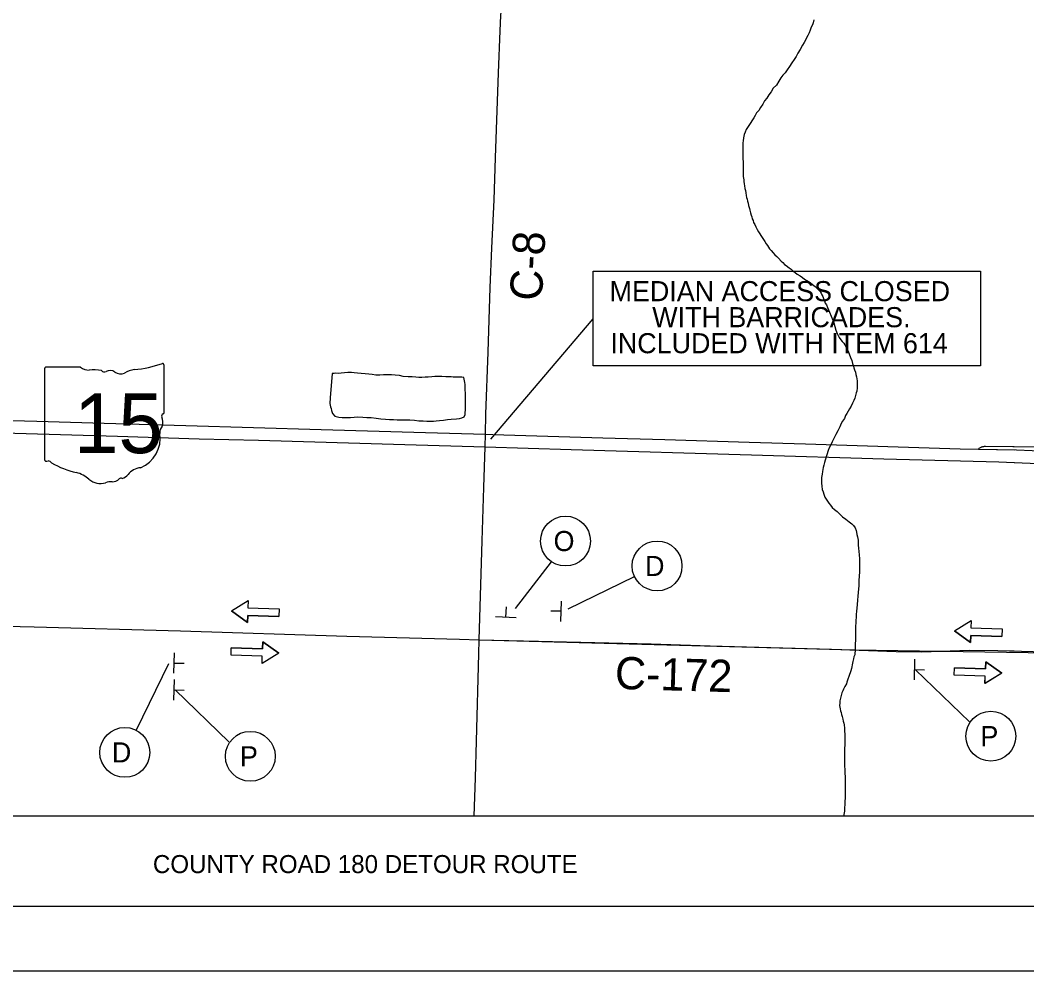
# Model space of a CAD drawing. Extents: x 1 to 1971, y -2 to 1107.
# Drawn here: x 1660.16 to 1667.97, y 1084.6 to 1091.98 of the extents above; entities that cross this region are included whole.
import ezdxf

# ---------------------------------------------------------------- set-up
doc = ezdxf.new("R2010")
doc.units = 0
for name, color, linetype in [('GM_X_County_Road', 7, 'Continuous'), ('GM_X_County_Road_Text', 7, 'Continuous'), ('GM_X_Interchange_Ramps', 7, 'Continuous'), ('GM_X_Minor_River', 7, 'Continuous'), ('GM_X_State_Route', 7, 'Continuous'), ('GM_X_State_Shield', 7, 'Continuous'), ('SH_Border', 7, 'Continuous'), ('SH_Cut_Line', 7, 'Continuous'), ('SH_Data', 7, 'Continuous'), ('SH_Text', 7, 'Continuous'), ('SN_P_Signs', 7, 'Continuous')]:
    doc.layers.add(name, color=color, linetype=linetype)

msp = doc.modelspace()

# ---------------------------------------------------------------- linework, layer by layer
at = {"layer": 'GM_X_County_Road'}
for points in [[(1663.7714, 1088.7638), (1663.7757, 1088.9203), (1663.7916, 1089.4012), (1663.8088, 1089.904), (1663.8208, 1090.2091), (1663.8384, 1090.5818), (1663.8499, 1090.9095), (1663.8728, 1091.5685), (1663.885, 1091.8932), (1663.8919, 1092.014), (1663.8966, 1092.0716), (1663.9012, 1092.1103), (1663.9093, 1092.1486), (1663.9186, 1092.1687), (1663.9325, 1092.1954), (1663.9457, 1092.2144), (1663.9663, 1092.2384)], [(1663.7714, 1088.7638), (1663.7757, 1088.9203), (1663.7916, 1089.4012), (1663.8088, 1089.904), (1663.8208, 1090.2091), (1663.8384, 1090.5818), (1663.8499, 1090.9095), (1663.8728, 1091.5685), (1663.885, 1091.8932), (1663.8919, 1092.014), (1663.8966, 1092.0716), (1663.9012, 1092.1103), (1663.9093, 1092.1486), (1663.9186, 1092.1687), (1663.9325, 1092.1954), (1663.9457, 1092.2144), (1663.9663, 1092.2384)], [(1663.7686, 1088.6652), (1663.7714, 1088.7638)], [(1663.7686, 1088.6652), (1663.7714, 1088.7638)], [(1663.7236, 1087.1696), (1663.7452, 1087.9363), (1663.76, 1088.3517), (1663.7686, 1088.6652)], [(1663.7236, 1087.1696), (1663.7452, 1087.9363), (1663.76, 1088.3517), (1663.7686, 1088.6652)], [(1656.5672, 1087.3642), (1656.5934, 1087.3633), (1657.0425, 1087.3482), (1657.533, 1087.3387), (1659.0643, 1087.2977), (1660.2675, 1087.2696), (1661.405, 1087.2377), (1662.6955, 1087.1976), (1663.5705, 1087.1736), (1663.7236, 1087.1696)], [(1656.5672, 1087.3642), (1656.5934, 1087.3633), (1657.0425, 1087.3482), (1657.533, 1087.3387), (1659.0643, 1087.2977), (1660.2675, 1087.2696), (1661.405, 1087.2377), (1662.6955, 1087.1976), (1663.5705, 1087.1736), (1663.7236, 1087.1696)], [(1663.6851, 1085.8005), (1663.6935, 1086.0994), (1663.7027, 1086.3836), (1663.7203, 1087.0616), (1663.7236, 1087.1696)], [(1663.6851, 1085.8005), (1663.6935, 1086.0994), (1663.7027, 1086.3836), (1663.7203, 1087.0616), (1663.7236, 1087.1696)], [(1663.7236, 1087.1696), (1664.183, 1087.1576), (1665.0579, 1087.1385), (1665.5171, 1087.1234), (1666.4577, 1087.0978), (1666.9606, 1087.0776), (1667.1575, 1087.0752), (1667.5292, 1087.089), (1667.748, 1087.0865), (1667.8763, 1087.0829)], [(1663.7236, 1087.1696), (1664.183, 1087.1576), (1665.0579, 1087.1385), (1665.5171, 1087.1234), (1666.4577, 1087.0978), (1666.9606, 1087.0776), (1667.1575, 1087.0752), (1667.5292, 1087.089), (1667.748, 1087.0865), (1669.3011, 1087.0422), (1669.9792, 1087.0232), (1670.236, 1087.0104), (1670.4866, 1086.997), (1670.9021, 1086.9648)]]:
    msp.add_lwpolyline(points, dxfattribs=at)
at = {"layer": 'GM_X_Interchange_Ramps'}
for points in [[(1667.8763, 1088.6662), (1667.6527, 1088.6689), (1667.6472, 1088.6687), (1667.642, 1088.6681), (1667.6368, 1088.6676), (1667.6307, 1088.6666), (1667.6242, 1088.6647), (1667.6203, 1088.6634), (1667.6166, 1088.6617), (1667.6121, 1088.6596), (1667.6075, 1088.6571), (1667.603, 1088.6535), (1667.5998, 1088.6492)], [(1668.0763, 1088.6637), (1667.6527, 1088.6689), (1667.6472, 1088.6687), (1667.642, 1088.6681), (1667.6368, 1088.6676), (1667.6307, 1088.6666), (1667.6242, 1088.6647), (1667.6203, 1088.6634), (1667.6166, 1088.6617), (1667.6121, 1088.6596), (1667.6075, 1088.6571), (1667.603, 1088.6535), (1667.5998, 1088.6492)]]:
    msp.add_lwpolyline(points, dxfattribs=at)
at = {"layer": 'GM_X_Minor_River'}
for points in [[(1666.3202, 1091.9803), (1666.3148, 1091.9563), (1666.3094, 1091.9402), (1666.3013, 1091.9215), (1666.2932, 1091.9001), (1666.2851, 1091.8788), (1666.2744, 1091.8574), (1666.2636, 1091.8387), (1666.2556, 1091.8227), (1666.2448, 1091.804), (1666.2341, 1091.7826), (1666.2153, 1091.7506), (1666.1965, 1091.7212), (1666.183, 1091.6945), (1666.1669, 1091.6705), (1666.1508, 1091.6464), (1666.132, 1091.6171), (1666.1132, 1091.5904), (1666.0971, 1091.569)], [(1666.0971, 1091.569), (1666.081, 1091.5503), (1666.0649, 1091.529), (1666.0488, 1091.5049), (1666.03, 1091.4729), (1666.0059, 1091.4489), (1665.9898, 1091.4222), (1665.971, 1091.3982), (1665.9549, 1091.3715), (1665.9388, 1091.3501), (1665.9253, 1091.3261), (1665.9065, 1091.2994), (1665.8931, 1091.2754), (1665.877, 1091.2567), (1665.8663, 1091.238), (1665.8555, 1091.2193), (1665.8394, 1091.1953), (1665.8313, 1091.1819), (1665.8206, 1091.1686), (1665.7964, 1091.1285), (1665.7883, 1091.1071), (1665.7803, 1091.0911), (1665.7776, 1091.0777), (1665.7749, 1091.0644), (1665.7721, 1091.0403), (1665.7694, 1091.0243), (1665.7694, 1091.0109), (1665.7694, 1090.9948), (1665.7693, 1090.9788), (1665.7693, 1090.9627), (1665.7692, 1090.9413), (1665.7692, 1090.9226), (1665.7691, 1090.9012), (1665.7718, 1090.8771), (1665.7717, 1090.8584), (1665.7717, 1090.8343), (1665.7716, 1090.8075), (1665.7716, 1090.7835), (1665.7715, 1090.7647), (1665.7742, 1090.7513), (1665.7768, 1090.7379), (1665.7768, 1090.7246), (1665.7794, 1090.7059), (1665.782, 1090.6925), (1665.7847, 1090.6711), (1665.79, 1090.655), (1665.7926, 1090.6362), (1665.7953, 1090.6175), (1665.7979, 1090.6015), (1665.8032, 1090.588), (1665.8058, 1090.572), (1665.8112, 1090.5559), (1665.8138, 1090.5399), (1665.8218, 1090.5158), (1665.8244, 1090.5024), (1665.8297, 1090.4809), (1665.835, 1090.4649), (1665.8403, 1090.4515), (1665.843, 1090.4354), (1665.851, 1090.422), (1665.8536, 1090.4059), (1665.8616, 1090.3925), (1665.8696, 1090.3738), (1665.8803, 1090.3524), (1665.8909, 1090.3336), (1665.9203, 1090.2907), (1665.9309, 1090.2746), (1665.9416, 1090.2585), (1665.9496, 1090.2424), (1665.9603, 1090.229), (1665.9683, 1090.2156), (1665.9762, 1090.2022), (1665.9896, 1090.1888), (1666.0056, 1090.1727), (1666.019, 1090.1566), (1666.0323, 1090.1432), (1666.0457, 1090.1298), (1666.067, 1090.1083), (1666.0804, 1090.0976), (1666.0937, 1090.0815), (1666.1071, 1090.0734), (1666.1284, 1090.0546), (1666.1445, 1090.0438), (1666.1578, 1090.0331), (1666.1765, 1090.0197), (1666.1925, 1090.0062), (1666.2139, 1089.9928), (1666.2326, 1089.9793), (1666.2486, 1089.9686), (1666.2673, 1089.9578), (1666.2914, 1089.9417), (1666.3101, 1089.9256), (1666.3315, 1089.9095), (1666.3448, 1089.8987), (1666.3582, 1089.8853), (1666.3688, 1089.8719), (1666.3768, 1089.8585), (1666.3821, 1089.8451), (1666.3901, 1089.8317), (1666.3955, 1089.8183), (1666.4034, 1089.7995)], [(1666.4034, 1089.7995), (1666.4087, 1089.7808), (1666.4194, 1089.7674), (1666.4274, 1089.7486), (1666.4354, 1089.7299), (1666.4434, 1089.7111), (1666.4673, 1089.6495), (1666.4753, 1089.6281), (1666.4833, 1089.6013), (1666.4912, 1089.5718), (1666.5019, 1089.5451), (1666.5179, 1089.5156), (1666.5312, 1089.4968), (1666.5419, 1089.4834), (1666.5525, 1089.47), (1666.5605, 1089.4566), (1666.5685, 1089.4432), (1666.5765, 1089.4298), (1666.5872, 1089.4083), (1666.5952, 1089.3869), (1666.6058, 1089.3601), (1666.6164, 1089.336), (1666.6217, 1089.3119), (1666.6297, 1089.2931), (1666.6324, 1089.2798), (1666.6377, 1089.2637), (1666.643, 1089.2449), (1666.6456, 1089.2289), (1666.6509, 1089.2101), (1666.6536, 1089.1941), (1666.6562, 1089.178), (1666.6562, 1089.162), (1666.6561, 1089.1405), (1666.6561, 1089.1245), (1666.6534, 1089.0978), (1666.6507, 1089.0844), (1666.6453, 1089.0657), (1666.6399, 1089.0443), (1666.6318, 1089.0256), (1666.621, 1089.0042), (1666.6103, 1088.9829), (1666.5969, 1088.9615), (1666.5861, 1088.9428), (1666.578, 1088.9241), (1666.5673, 1088.9108), (1666.5592, 1088.8867), (1666.5431, 1088.8653), (1666.5324, 1088.8467), (1666.5216, 1088.8226), (1666.5082, 1088.7905), (1666.492, 1088.7612), (1666.4759, 1088.7318), (1666.4625, 1088.7051), (1666.4517, 1088.681), (1666.441, 1088.6597), (1666.4329, 1088.6383), (1666.4086, 1088.5635), (1666.4032, 1088.5447), (1666.3978, 1088.5233), (1666.3925, 1088.5073), (1666.3897, 1088.4913), (1666.387, 1088.4752), (1666.3843, 1088.4538), (1666.3816, 1088.4298), (1666.3815, 1088.4084), (1666.3815, 1088.3843), (1666.3841, 1088.3602), (1666.3867, 1088.3361), (1666.392, 1088.3174), (1666.3973, 1088.2986), (1666.4053, 1088.2772), (1666.416, 1088.2611), (1666.4266, 1088.245), (1666.4373, 1088.2289), (1666.4506, 1088.2128), (1666.464, 1088.1967), (1666.48, 1088.1806), (1666.5014, 1088.1645), (1666.5254, 1088.1403), (1666.5441, 1088.1242), (1666.5681, 1088.1054), (1666.5948, 1088.0839), (1666.6162, 1088.0678), (1666.6296, 1088.0571), (1666.6429, 1088.0383), (1666.6482, 1088.0169), (1666.6508, 1088.0035), (1666.6535, 1087.9874), (1666.6588, 1087.9687), (1666.6614, 1087.9553), (1666.6641, 1087.9419), (1666.664, 1087.9232), (1666.664, 1087.9045), (1666.6666, 1087.8804), (1666.6692, 1087.8536), (1666.6719, 1087.8295), (1666.6744, 1087.7974), (1666.6744, 1087.776), (1666.6743, 1087.7493), (1666.6743, 1087.7252), (1666.6742, 1087.6957)], [(1662.5812, 1089.2365), (1662.5647, 1089.0466), (1662.5646, 1089.0038), (1662.5672, 1088.9771), (1662.5725, 1088.9637), (1662.5751, 1088.9476), (1662.5831, 1088.9262), (1662.6018, 1088.9047), (1662.6339, 1088.8966), (1662.658, 1088.8938), (1662.6713, 1088.8938), (1662.6874, 1088.8937), (1662.7061, 1088.8937), (1662.7249, 1088.8936), (1662.7516, 1088.8962), (1662.7811, 1088.8988), (1662.8185, 1088.896), (1662.8506, 1088.8932), (1662.8854, 1088.8931), (1662.9228, 1088.8876), (1662.9603, 1088.8848), (1662.9951, 1088.8821), (1663.0272, 1088.8793), (1663.0566, 1088.8792), (1663.086, 1088.8764), (1663.1128, 1088.8763), (1663.1422, 1088.8762), (1663.1851, 1088.8761), (1663.2198, 1088.8733), (1663.2546, 1088.8679), (1663.2867, 1088.8677), (1663.3161, 1088.865), (1663.3429, 1088.8649), (1663.367, 1088.8648), (1663.3884, 1088.8674), (1663.4151, 1088.87), (1663.4446, 1088.8726), (1663.4767, 1088.8778), (1663.5061, 1088.8804), (1663.5463, 1088.883), (1663.5704, 1088.8856), (1663.5891, 1088.8909), (1663.6052, 1088.8988), (1663.6133, 1088.9175), (1663.6133, 1088.9309), (1663.616, 1088.9523), (1663.6161, 1088.9978), (1663.6162, 1089.0138), (1663.6162, 1089.0326), (1663.6162, 1089.0486)], [(1663.6162, 1089.0486), (1663.6163, 1089.0673), (1663.6163, 1089.0834), (1663.6137, 1089.1075), (1663.6137, 1089.1289), (1663.6138, 1089.1503), (1663.6112, 1089.1664), (1663.6085, 1089.1797), (1663.6032, 1089.2038), (1663.5872, 1089.2066), (1663.5738, 1089.2066), (1663.5551, 1089.2067), (1663.5363, 1089.2067), (1663.5203, 1089.2068), (1663.5042, 1089.2095), (1663.4855, 1089.2096), (1663.4641, 1089.2096), (1663.432, 1089.2124), (1663.4025, 1089.2125), (1663.3785, 1089.2126), (1663.3544, 1089.21), (1663.3276, 1089.2074), (1663.3035, 1089.2075), (1663.2768, 1089.2049), (1663.2554, 1089.2049), (1663.2313, 1089.2077), (1663.2019, 1089.2105), (1663.1724, 1089.2106), (1663.1323, 1089.2134), (1663.1029, 1089.2188), (1663.0708, 1089.2216), (1663.0413, 1089.2244), (1663.0119, 1089.2245), (1662.9798, 1089.2246), (1662.9504, 1089.222), (1662.9209, 1089.2221), (1662.8915, 1089.2275), (1662.8648, 1089.2303), (1662.7792, 1089.2386), (1662.7524, 1089.2413), (1662.731, 1089.2441), (1662.7043, 1089.2442), (1662.6775, 1089.2416), (1662.6507, 1089.239), (1662.6293, 1089.2364), (1662.6106, 1089.2391), (1662.5972, 1089.2365), (1662.5865, 1089.2365), (1662.5812, 1089.2365)], [(1666.6742, 1087.6957), (1666.6714, 1087.6289), (1666.6713, 1087.6101), (1666.6713, 1087.5887), (1666.6686, 1087.5647), (1666.6658, 1087.5352), (1666.6631, 1087.5085), (1666.6603, 1087.4764), (1666.6576, 1087.4443), (1666.6548, 1087.4149), (1666.6521, 1087.3908), (1666.6494, 1087.3667), (1666.6493, 1087.3427), (1666.6466, 1087.3213), (1666.6465, 1087.2972), (1666.6438, 1087.2785), (1666.6438, 1087.2544), (1666.6437, 1087.2196), (1666.6436, 1087.1902), (1666.6435, 1087.1634), (1666.6408, 1087.1394), (1666.6408, 1087.1179), (1666.6407, 1087.0965), (1666.6407, 1087.0805), (1666.638, 1087.0671), (1666.6379, 1087.0537), (1666.6326, 1087.0377), (1666.6299, 1087.0217), (1666.6245, 1087.0003), (1666.619, 1086.9762), (1666.6163, 1086.9602), (1666.6136, 1086.9468), (1666.6082, 1086.9281), (1666.6028, 1086.9121), (1666.5975, 1086.8987), (1666.5921, 1086.8853), (1666.584, 1086.864), (1666.5759, 1086.8399), (1666.5732, 1086.8265), (1666.5625, 1086.8079), (1666.5517, 1086.7865), (1666.5463, 1086.7731), (1666.5383, 1086.7571), (1666.5221, 1086.6956), (1666.522, 1086.6769), (1666.5193, 1086.6582), (1666.5246, 1086.6341), (1666.5272, 1086.618), (1666.5326, 1086.6046), (1666.5352, 1086.5886), (1666.5405, 1086.5751), (1666.5458, 1086.5537), (1666.5485, 1086.5377), (1666.5538, 1086.5216), (1666.5564, 1086.5082), (1666.5591, 1086.4841), (1666.559, 1086.4708), (1666.559, 1086.4574), (1666.5616, 1086.4386), (1666.5616, 1086.4146), (1666.5614, 1086.3611), (1666.5587, 1086.3183), (1666.5586, 1086.2835), (1666.5585, 1086.2487), (1666.5584, 1086.2166), (1666.5584, 1086.1898), (1666.561, 1086.1631), (1666.5609, 1086.1336), (1666.5635, 1086.1069), (1666.5635, 1086.0721), (1666.5634, 1086.0453), (1666.5633, 1086.0106), (1666.5632, 1085.9785), (1666.5631, 1085.9437), (1666.5604, 1085.9142), (1666.5604, 1085.8902), (1666.5576, 1085.8661), (1666.5576, 1085.8393), (1666.5548, 1085.8126), (1666.5537, 1085.8005)]]:
    msp.add_lwpolyline(points, dxfattribs=at)
at = {"layer": 'GM_X_State_Route'}
for points in [[(1653.1763, 1089.0716), (1653.7087, 1089.0563), (1654.4064, 1089.0358), (1654.8887, 1089.0196), (1655.371, 1089.0075), (1656.2656, 1088.9829), (1656.6538, 1088.9713), (1657.5335, 1088.9451), (1659.6102, 1088.8844), (1660.288, 1088.8659), (1660.8126, 1088.8494), (1661.4466, 1088.8312), (1662.4959, 1088.8007), (1663.3048, 1088.777), (1663.7714, 1088.7638), (1663.8294, 1088.7624), (1664.6819, 1088.737), (1665.1629, 1088.7239), (1665.8187, 1088.7038), (1666.2558, 1088.6901), (1667.4561, 1088.6514), (1667.5998, 1088.6492), (1667.8763, 1088.6439)], [(1653.1763, 1088.972), (1654.1058, 1088.9448), (1655.1549, 1088.9137), (1655.8542, 1088.8935), (1656.6489, 1088.8688), (1657.2445, 1088.8506), (1657.6825, 1088.8393), (1658.51, 1088.8187), (1659.3192, 1088.7948), (1660.9157, 1088.748), (1661.55, 1088.7295), (1662.0093, 1088.7178), (1663.1466, 1088.6833), (1663.7686, 1088.6652), (1664.4369, 1088.6454), (1665.8366, 1088.6041), (1666.8645, 1088.5732), (1667.7577, 1088.5488), (1667.8763, 1088.5445)], [(1653.1763, 1088.972), (1654.1058, 1088.9448), (1655.1549, 1088.9137), (1655.8542, 1088.8935), (1656.6489, 1088.8688), (1657.2445, 1088.8506), (1657.6825, 1088.8393), (1658.51, 1088.8187), (1659.3192, 1088.7948), (1660.9157, 1088.748), (1661.55, 1088.7295), (1662.0093, 1088.7178), (1663.1466, 1088.6833), (1663.7686, 1088.6652), (1664.4369, 1088.6454), (1665.8366, 1088.6041), (1666.8645, 1088.5732), (1667.7577, 1088.5488), (1668.0608, 1088.5378), (1669.2047, 1088.5077), (1669.5547, 1088.5002), (1670.1889, 1088.4798), (1670.4622, 1088.472)], [(1659.6102, 1088.8844), (1660.288, 1088.8659), (1660.8126, 1088.8494), (1661.4466, 1088.8312), (1662.4959, 1088.8007), (1663.3048, 1088.777), (1663.7714, 1088.7638), (1663.8294, 1088.7624), (1664.6819, 1088.737), (1665.1629, 1088.7239), (1665.8187, 1088.7038), (1666.2558, 1088.6901), (1667.4561, 1088.6514), (1667.5998, 1088.6492), (1667.8954, 1088.6435), (1668.1374, 1088.6337), (1668.7912, 1088.6143), (1669.5117, 1088.5931), (1670.4659, 1088.5658), (1670.98, 1088.5507), (1672.2022, 1088.5164)]]:
    msp.add_lwpolyline(points, dxfattribs=at)
at = {"layer": 'GM_X_State_Shield'}
for p, q in [((1660.3478, 1089.2721), (1660.3478, 1088.5677)), ((1660.6287, 1089.2842), (1660.3569, 1089.2842)), ((1661.2759, 1088.9332), (1661.2759, 1089.3017)), ((1661.2758, 1088.9333), (1661.2759, 1088.9332))]:
    msp.add_line(p, q, dxfattribs=at)
for centre, radius, start, end in [((1660.3584, 1089.2736), 0.0108, 98.1301, 188.1301), ((1660.6934, 1089.366), 0.1043, 231.61951, 271.11188), ((1660.9453, 1090.2446), 0.9842, 275.84447, 288.90645), ((1661.2656, 1089.3032), 0.0103, 351.86209, 97.738), ((1660.728, 1088.8888), 0.3744, 80.48669, 94.98827), ((1660.813, 1089.2773), 0.0301, 219.79206, 297.10237), ((1660.8572, 1089.1958), 0.0626, 54.46668, 119.14113), ((1660.9379, 1089.3075), 0.0753, 233.85621, 294.82819), ((1661.0708, 1089.0691), 0.198, 97.34618, 120.76885), ((1661.2735, 1088.9061), 0.016, 107.94398, 210.33697), ((1661.1718, 1088.8596), 0.096, 340.03296, 23.64957), ((1661.2649, 1088.9318), 0.0111, 289.60381, 7.73413), ((1661.3129, 1088.779), 0.0698, 136.8065, 186.92959), ((1661.0004, 1088.7321), 0.2462, 292.30889, 8.98584), ((1660.3585, 1088.5661), 0.0108, 171.95839, 258.30661), ((1660.3601, 1088.6382), 0.0828, 267.33899, 280.60386), ((1660.3771, 1088.527), 0.0298, 29.74838, 93.27175), ((1660.7539, 1089.1599), 0.7108, 240.41292, 257.1985), ((1661.1042, 1088.3699), 0.1348, 94.40312, 142.57675), ((1660.542, 1088.2512), 0.2224, 47.18416, 75.83597), ((1660.7826, 1088.5236), 0.1411, 230.70037, 286.29184), ((1660.8744, 1088.4708), 0.0752, 268.77702, 315.54927), ((1660.9424, 1088.4026), 0.0212, 65.75173, 132.64842), ((1660.9334, 1088.4994), 0.0795, 282.87319, 323.27711), ((1660.8641, 1088.28), 0.116, 85.69512, 111.20995)]:
    msp.add_arc(centre, radius, start, end, dxfattribs=at)
at = {"layer": 'SH_Border'}
msp.add_lwpolyline([(1652.9632, 1106.1005), (1684.9632, 1106.1005), (1684.9632, 1085.1005), (1652.9632, 1085.1005)], close=True, dxfattribs=at)
at = {"layer": 'SH_Cut_Line'}
msp.add_lwpolyline([(1651.4632, 1084.6005), (1685.4632, 1084.6005), (1685.4632, 1106.6005), (1651.4632, 1106.6005)], close=True, dxfattribs=at)
at = {"layer": 'SH_Data'}
msp.add_lwpolyline([(1653.1763, 1105.4005), (1672.2022, 1105.4005), (1672.2022, 1085.8005), (1653.1763, 1085.8005)], close=True, dxfattribs=at)
at = {"layer": 'SH_Text'}
for p, q in [((1663.8131, 1088.726), (1664.6089, 1089.6593)), ((1664.0041, 1087.411), (1664.2844, 1087.7753)), ((1664.4126, 1087.4105), (1664.9284, 1087.6598)), ((1661.7995, 1087.3928), (1661.9297, 1087.4733)), ((1661.9297, 1087.4733), (1661.9278, 1087.4163)), ((1661.9278, 1087.4163), (1662.1697, 1087.4083)), ((1662.1697, 1087.4083), (1662.1678, 1087.3503)), ((1661.7995, 1087.3928), (1661.9241, 1087.3038)), ((1661.9241, 1087.3038), (1661.9259, 1087.3583)), ((1661.9259, 1087.3583), (1662.1678, 1087.3503)), ((1667.4125, 1087.2379), (1667.5427, 1087.3184)), ((1667.5427, 1087.3184), (1667.5408, 1087.2615)), ((1667.5408, 1087.2615), (1667.7827, 1087.2534)), ((1667.7827, 1087.2534), (1667.7808, 1087.1955)), ((1663.7236, 1087.1696), (1666.6353, 1087.0907)), ((1667.4125, 1087.2379), (1667.5371, 1087.1489)), ((1667.5371, 1087.1489), (1667.5389, 1087.2035)), ((1667.5389, 1087.2035), (1667.7808, 1087.1955)), ((1661.7967, 1087.0497), (1661.7986, 1087.1077)), ((1662.0405, 1087.0996), (1661.7986, 1087.1077)), ((1662.0423, 1087.1542), (1662.0405, 1087.0996)), ((1662.1669, 1087.0652), (1662.0423, 1087.1542)), ((1666.6353, 1087.0907), (1668.6047, 1087.0621)), ((1662.0386, 1087.0417), (1661.7967, 1087.0497)), ((1662.1669, 1087.0652), (1662.0367, 1086.9847)), ((1662.0367, 1086.9847), (1662.0386, 1087.0417)), ((1661.3119, 1086.9822), (1661.0587, 1086.4683)), ((1667.1102, 1086.9366), (1667.5289, 1086.5333)), ((1667.4096, 1086.8949), (1667.4116, 1086.9528)), ((1667.6535, 1086.9448), (1667.4116, 1086.9528)), ((1667.6553, 1086.9994), (1667.6535, 1086.9448)), ((1667.7799, 1086.9104), (1667.6553, 1086.9994)), ((1667.6515, 1086.8868), (1667.4096, 1086.8949)), ((1667.7799, 1086.9104), (1667.6496, 1086.8299)), ((1667.6496, 1086.8299), (1667.6515, 1086.8868)), ((1661.3615, 1086.78), (1661.7801, 1086.3767))]:
    msp.add_line(p, q, dxfattribs=at)
for points in [[(1664.6089, 1090.0297), (1667.6143, 1090.0297), (1667.6143, 1089.2942), (1664.6089, 1089.2942)], [(1662.1678, 1087.3503), (1661.9259, 1087.3583), (1661.9241, 1087.3038), (1661.7995, 1087.3928), (1661.9297, 1087.4733), (1661.9278, 1087.4163), (1662.1697, 1087.4083)], [(1667.7808, 1087.1954), (1667.5389, 1087.2035), (1667.5371, 1087.1489), (1667.4124, 1087.2379), (1667.5427, 1087.3184), (1667.5408, 1087.2615), (1667.7827, 1087.2534)], [(1661.7986, 1087.1077), (1662.0405, 1087.0996), (1662.0423, 1087.1542), (1662.1669, 1087.0652), (1662.0367, 1086.9847), (1662.0386, 1087.0417), (1661.7967, 1087.0497)], [(1667.4116, 1086.9528), (1667.6535, 1086.9448), (1667.6553, 1086.9994), (1667.7799, 1086.9104), (1667.6497, 1086.8299), (1667.6515, 1086.8868), (1667.4096, 1086.8949)]]:
    msp.add_lwpolyline(points, close=True, dxfattribs=at)
msp.add_lwpolyline([(1656.5672, 1087.3642), (1656.5934, 1087.3633), (1657.0425, 1087.3482), (1657.533, 1087.3387), (1659.0643, 1087.2977), (1660.2675, 1087.2696), (1661.405, 1087.2377), (1662.6955, 1087.1976), (1663.5705, 1087.1736), (1663.7236, 1087.1696)], dxfattribs=at)
for centre in [(1664.3932, 1087.9355), (1665.1037, 1087.742), (1667.6949, 1086.4217), (1660.9711, 1086.2957), (1661.9461, 1086.2651)]:
    msp.add_circle(centre, 0.1936, dxfattribs=at)
at = {"layer": 'SN_P_Signs'}
for p, q in [((1663.93, 1087.3461), (1663.9341, 1087.426)), ((1664.3578, 1087.3103), (1664.3625, 1087.4702)), ((1663.8501, 1087.3502), (1664.0099, 1087.342)), ((1664.3601, 1087.3903), (1664.2802, 1087.3926)), ((1661.3555, 1087.0691), (1661.3508, 1086.9092)), ((1667.1032, 1087.018), (1667.0985, 1086.858)), ((1661.3532, 1086.9891), (1661.4331, 1086.9868)), ((1667.1009, 1086.938), (1667.1808, 1086.9356)), ((1661.3545, 1086.8614), (1661.3497, 1086.7014)), ((1661.3521, 1086.7814), (1661.4321, 1086.779))]:
    msp.add_line(p, q, dxfattribs=at)

# ---------------------------------------------------------------- texts
at = {"layer": 'GM_X_County_Road_Text'}
for s, rotation, p in [('C-8', 86.97063, (1664.2093, 1089.7954)), ('C-172', 358.34755, (1664.7742, 1086.7886))]:
    msp.add_text(s, height=0.25, rotation=rotation, dxfattribs=at).set_placement(p)
at = {"layer": 'GM_X_State_Shield'}
msp.add_text('15', height=0.46406, dxfattribs=at).set_placement((1660.5768, 1088.6174))
at = {"layer": 'SH_Text'}
for s, height, p in [('MEDIAN ACCESS CLOSED', 0.156, (1664.7353, 1089.7964)), ('WITH BARRICADES. ', 0.156, (1665.0663, 1089.5945)), ('INCLUDED WITH ITEM 614', 0.156, (1664.7413, 1089.3926)), ('O', 0.156, (1664.3005, 1087.8575)), ('D', 0.156, (1665.0107, 1087.664)), ('P', 0.156, (1667.6141, 1086.3437)), ('D', 0.156, (1660.8714, 1086.2177)), ('P', 0.156, (1661.8654, 1086.1871)), ('COUNTY ROAD 180 DETOUR ROUTE', 0.14, (1661.1897, 1085.359))]:
    msp.add_text(s, height=height, dxfattribs=at).set_placement(p)

doc.saveas('drawing.dxf')
